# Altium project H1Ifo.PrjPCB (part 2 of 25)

## Sheet IfoAux1.SchDoc: D1800185
size C; Engineer: Daniel Sigg; DocumentNumber: 5; Revision: 4; SheetNumber: 5; SheetTotal: 8
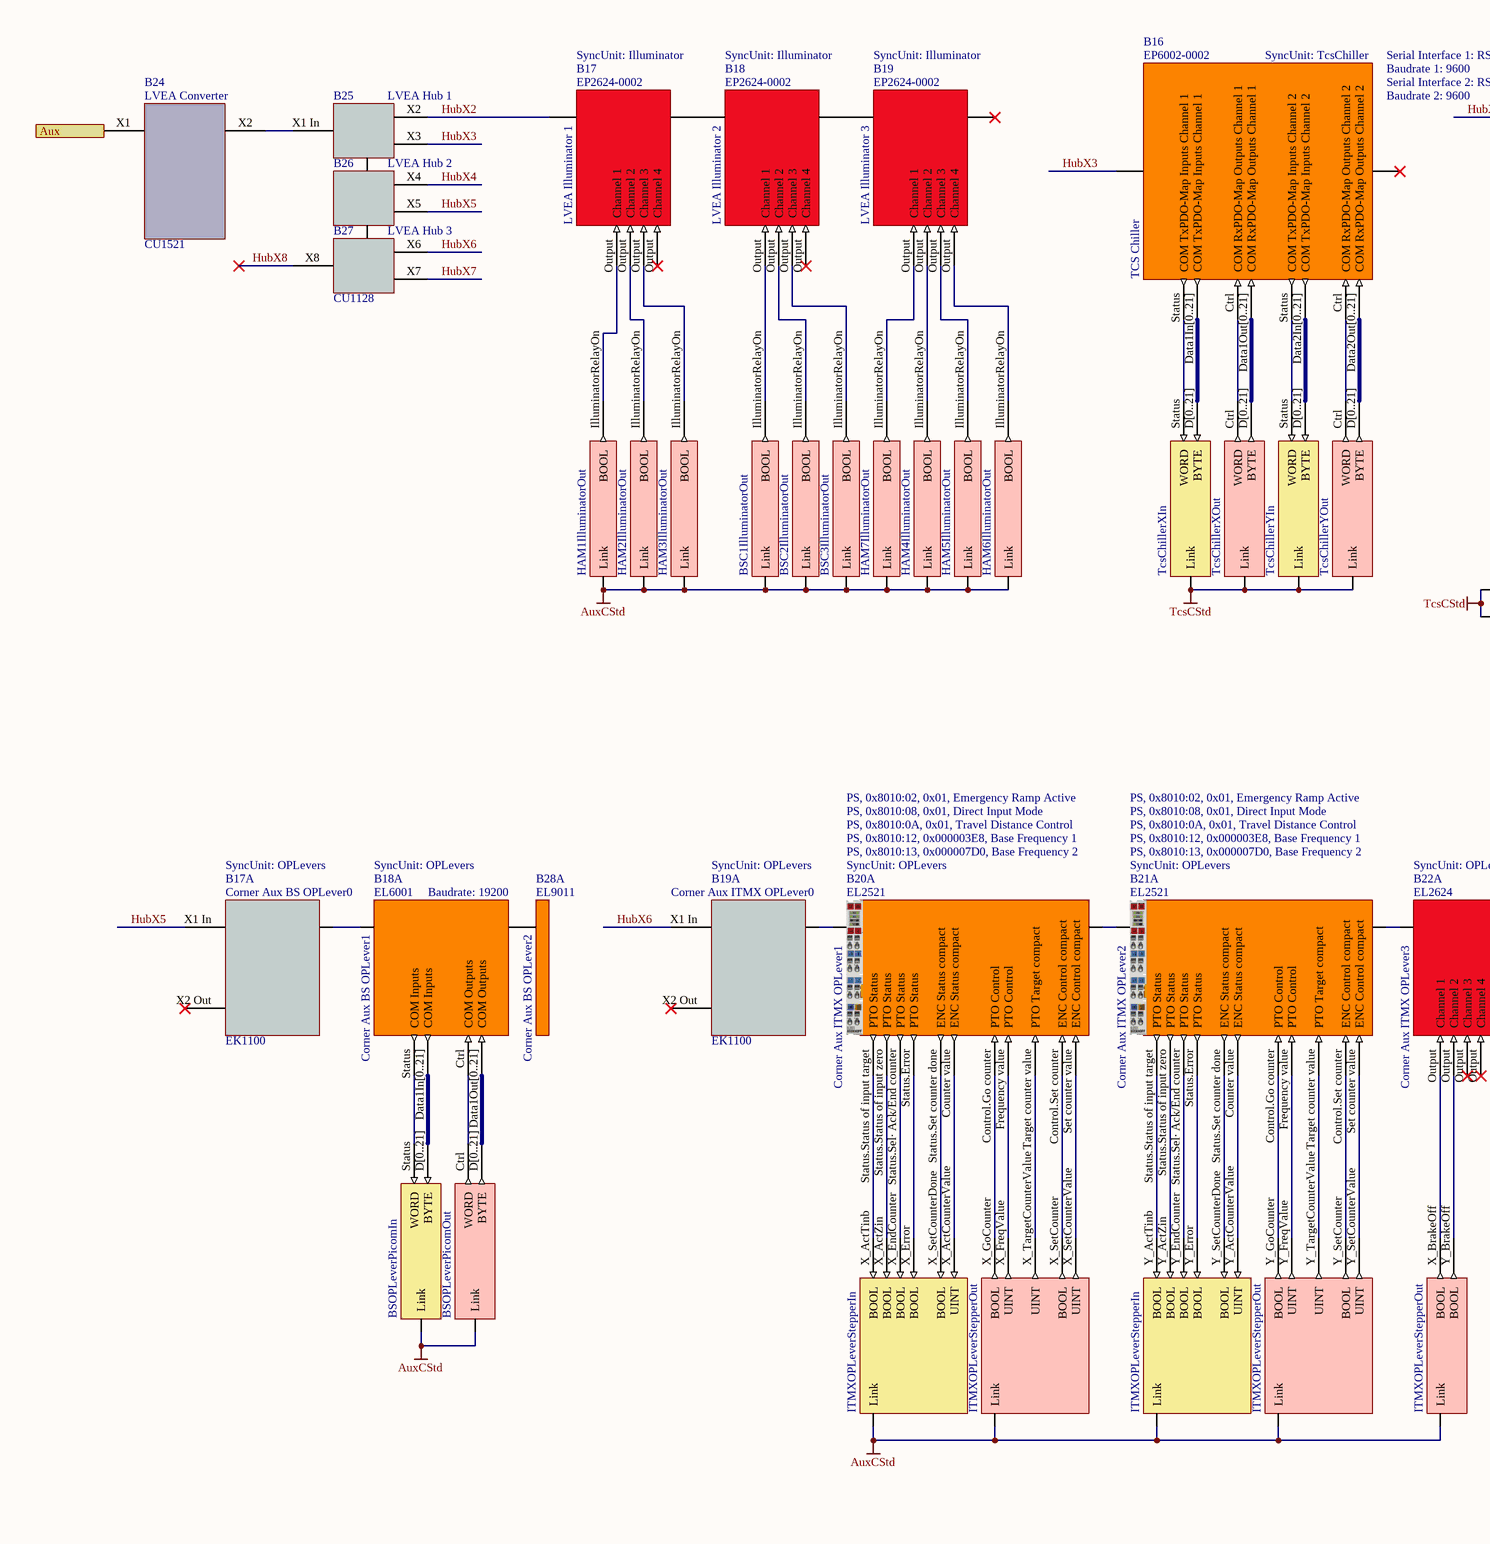
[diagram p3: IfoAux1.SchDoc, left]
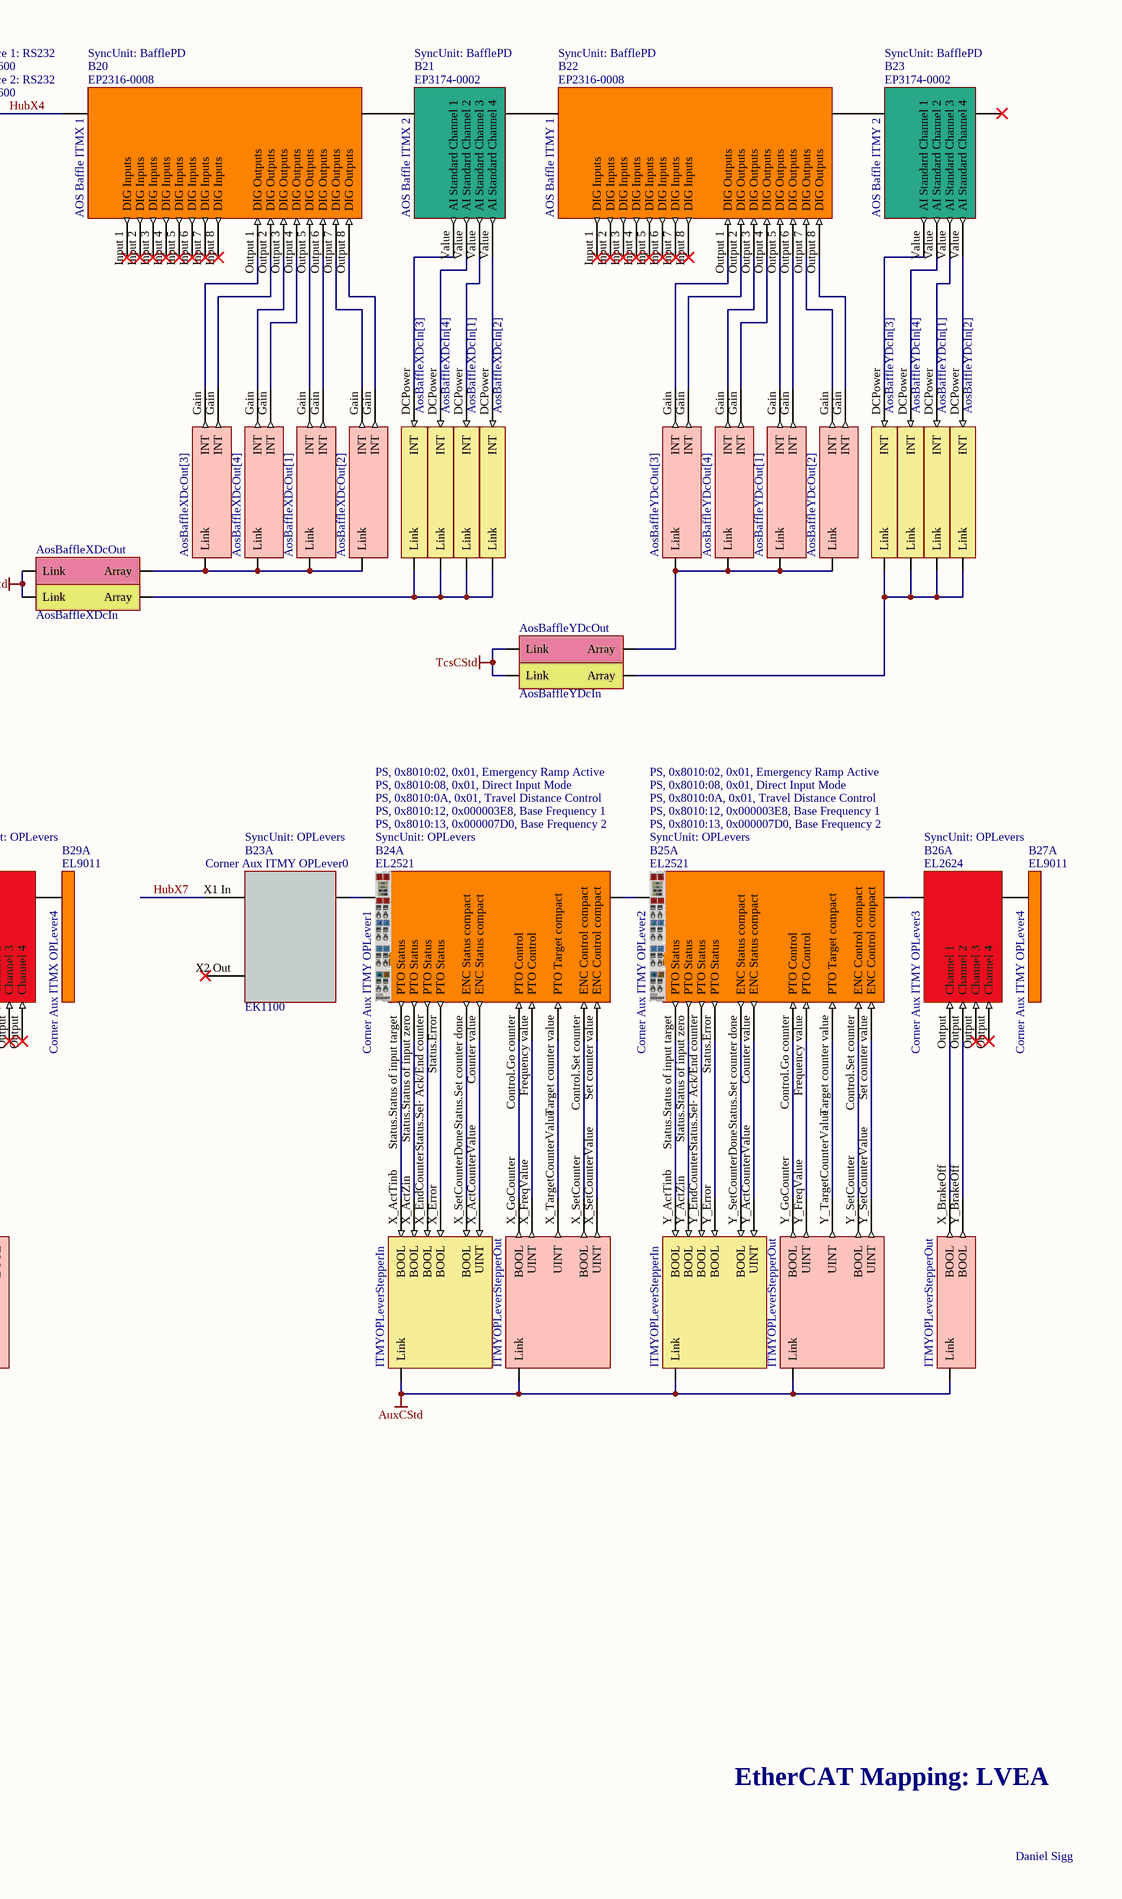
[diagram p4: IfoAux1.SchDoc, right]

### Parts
B16  TCS Chiller  Part Number: EP6002-0002  SyncUnit: TcsChiller  Baudrate 1: 9600  Serial Interface 1: RS232  (mechanical)
B17  LVEA Illuminator 1  Part Number: EP2624-0002  SyncUnit: Illuminator  (mechanical)
B17A  Corner Aux BS OPLever0  SyncUnit: OPLevers  Part Number: EK1100  (mechanical)
B18  LVEA Illuminator 2  Part Number: EP2624-0002  SyncUnit: Illuminator  (mechanical)
B18A  Corner Aux BS OPLever1  SyncUnit: OPLevers  Part Number: EL6001  Baudrate: 19200  (mechanical)
B19  LVEA Illuminator 3  Part Number: EP2624-0002  SyncUnit: Illuminator  (mechanical)
B19A  Corner Aux ITMX OPLever0  SyncUnit: OPLevers  Part Number: EK1100  (mechanical)
B20  AOS Baffle ITMX 1  Part Number: EP2316-0008  SyncUnit: BafflePD  (mechanical)
B20A  Corner Aux ITMX OPLever1  SyncUnit: OPLevers  Part Number: EL2521  Init0Cmd: PS, 0x8010:02, 0x01, Emergency Ramp Active  Init1Cmd: PS, 0x8010:08, 0x01, Direct Input Mode  Init2Cmd: PS, 0x8010:0A, 0x01, Travel Distance Control  Init3Cmd: PS, 0x8010:12, 0x000003E8, Base Frequency 1  Init4Cmd: PS, 0x8010:13, 0x000007D0, Base Frequency 2  (mechanical)
B21  AOS Baffle ITMX 2  Part Number: EP3174-0002  SyncUnit: BafflePD  (mechanical)
B21A  Corner Aux ITMX OPLever2  SyncUnit: OPLevers  Part Number: EL2521  Init0Cmd: PS, 0x8010:02, 0x01, Emergency Ramp Active  Init1Cmd: PS, 0x8010:08, 0x01, Direct Input Mode  Init2Cmd: PS, 0x8010:0A, 0x01, Travel Distance Control  Init3Cmd: PS, 0x8010:12, 0x000003E8, Base Frequency 1  Init4Cmd: PS, 0x8010:13, 0x000007D0, Base Frequency 2  (mechanical)
B22  AOS Baffle ITMY 1  Part Number: EP2316-0008  SyncUnit: BafflePD  (mechanical)
B22A  Corner Aux ITMX OPLever3  SyncUnit: OPLevers  Part Number: EL2624  (mechanical)
B23  AOS Baffle ITMY 2  Part Number: EP3174-0002  SyncUnit: BafflePD  (mechanical)
B23A  Corner Aux ITMY OPLever0  SyncUnit: OPLevers  Part Number: EK1100  (mechanical)
B24  LVEA Converter  Part Number: CU1521  (mechanical)
B24A  Corner Aux ITMY OPLever1  SyncUnit: OPLevers  Part Number: EL2521  Init0Cmd: PS, 0x8010:02, 0x01, Emergency Ramp Active  Init1Cmd: PS, 0x8010:08, 0x01, Direct Input Mode  Init2Cmd: PS, 0x8010:0A, 0x01, Travel Distance Control  Init3Cmd: PS, 0x8010:12, 0x000003E8, Base Frequency 1  Init4Cmd: PS, 0x8010:13, 0x000007D0, Base Frequency 2  (mechanical)
B25  LVEA Hub 1  Part Number: CU1128  (mechanical)
B25A  Corner Aux ITMY OPLever2  SyncUnit: OPLevers  Part Number: EL2521  Init0Cmd: PS, 0x8010:02, 0x01, Emergency Ramp Active  Init1Cmd: PS, 0x8010:08, 0x01, Direct Input Mode  Init2Cmd: PS, 0x8010:0A, 0x01, Travel Distance Control  Init3Cmd: PS, 0x8010:12, 0x000003E8, Base Frequency 1  Init4Cmd: PS, 0x8010:13, 0x000007D0, Base Frequency 2  (mechanical)
B26  LVEA Hub 2  (mechanical)
B26A  Corner Aux ITMY OPLever3  SyncUnit: OPLevers  Part Number: EL2624  (mechanical)
B27  LVEA Hub 3  (mechanical)
B27A  Corner Aux ITMY OPLever4  Part Number: EL9011  (mechanical)
B28A  Corner Aux BS OPLever2  Part Number: EL9011  (mechanical)
B29A  Corner Aux ITMX OPLever4  Part Number: EL9011  (mechanical)
V105  HAM1IlluminatorOut  (no BOM)
V105A  BSOPLeverPicomIn  (no BOM)
V106  HAM2IlluminatorOut  (no BOM)
V106A  BSOPLeverPicomOut  (no BOM)
V107  HAM3IlluminatorOut  (no BOM)
V107A  ITMXOPLeverStepperIn  (parts A,B of 2)  (no BOM)
V108  BSC1IlluminatorOut  (no BOM)
V108A  ITMXOPLeverStepperOut  (parts A,B,C of 3)  (no BOM)
V109  BSC2IlluminatorOut  (no BOM)
V109A  ITMYOPLeverStepperIn  (parts A,B of 2)  (no BOM)
V110  BSC3IlluminatorOut  (no BOM)
V110A  ITMYOPLeverStepperOut  (parts A,B,C of 3)  (no BOM)
V111  HAM4IlluminatorOut  (no BOM)
V112  HAM5IlluminatorOut  (no BOM)
V113  HAM6IlluminatorOut  (no BOM)
V114  AosBaffleXDcOut[3]  (no BOM)
V115  AosBaffleXDcOut[4]  (no BOM)
V116  AosBaffleXDcOut[1]  (no BOM)
V117  AosBaffleXDcOut[2]  (no BOM)
V118  AosBaffleXDcIn[3]  (no BOM)
V119  AosBaffleXDcIn[4]  (no BOM)
V120  AosBaffleXDcIn[1]  (no BOM)
V121  AosBaffleXDcIn[2]  (no BOM)
V122  AosBaffleYDcOut[3]  (no BOM)
V123  AosBaffleYDcOut[4]  (no BOM)
V124  AosBaffleYDcOut[1]  (no BOM)
V129  AosBaffleYDcOut[2]  (no BOM)
V130  AosBaffleYDcIn[3]  (no BOM)
V133  AosBaffleYDcIn[4]  (no BOM)
V134  AosBaffleYDcIn[1]  (no BOM)
V135  AosBaffleYDcIn[2]  (no BOM)
V136  AosBaffleXDcOut  (no BOM)
V137  TcsChillerXIn  (no BOM)
V138  TcsChillerXOut  (no BOM)
V139  TcsChillerYIn  (no BOM)
V140  TcsChillerYOut  (no BOM)
V141  AosBaffleXDcIn  (no BOM)
V142  AosBaffleYDcOut  (no BOM)
V143  AosBaffleYDcIn  (no BOM)
V842  HAM7IlluminatorOut  (no BOM)

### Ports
Aux

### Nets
AuxCStd: V105.0(Link) V105A.?1(Link) V106.0(Link) V106A.?1(Link) V107.0(Link) V107A.0(Link) V107A.1(Link) V108.0(Link) V108A.0(Link) V108A.1(Link) V108A.2(Link) V109.0(Link) V109A.0(Link) V109A.1(Link) V110.0(Link) V110A.0(Link) V110A.1(Link) V110A.2(Link) V111.0(Link) V112.0(Link) V113.0(Link) V842.0(Link)
TcsCStd: V136.?1(Link) V137.?1(Link) V138.?1(Link) V139.?1(Link) V140.?1(Link) V141.?1(Link) V142.?1(Link) V143.?1(Link)
HubX2: B17.?2(A) B25.X2(D)
HubX3: B16.?2(A) B25.X3(B)
HubX4: B20.?2(A) B26.X4(D)
HubX5: B17A.X1_In(A) B26.X5(B)
HubX6: B19A.X1_In(A) B27.X6(D)
HubX7: B23A.X1_In(A) B27.X7(B)
HubX8: B27.X8(C)
NetB16_Ctrl: B16.Ctrl(COM_RxPDO-Map_Outputs_Channel_1) V138.Ctrl(WORD)
NetB16_Ctrl: B16.Ctrl(COM_RxPDO-Map_Outputs_Channel_2) V140.Ctrl(WORD)  [a separate net that carries the same name]
NetB16_Data1In[0..21]: B16.Data1In[0..21](COM_TxPDO-Map_Inputs_Channel_1) V137.D[0..21](BYTE)
NetB16_Data1Out[0..21]: B16.Data1Out[0..21](COM_RxPDO-Map_Outputs_Channel_1) V138.D[0..21](BYTE)
NetB16_Data2In[0..21]: B16.Data2In[0..21](COM_TxPDO-Map_Inputs_Channel_2) V139.D[0..21](BYTE)
NetB16_Data2Out[0..21]: B16.Data2Out[0..21](COM_RxPDO-Map_Outputs_Channel_2) V140.D[0..21](BYTE)
NetB16_Status: B16.Status(COM_TxPDO-Map_Inputs_Channel_1) V137.Status(WORD)
NetB16_Status: B16.Status(COM_TxPDO-Map_Inputs_Channel_2) V139.Status(WORD)  [a separate net that carries the same name]
NetB17_?1: B17.?1(B) B18.?2(A)
NetB17_Output: B17.Output(Channel_1) V105.IlluminatorRelayOn(BOOL)
NetB17_Output: B17.Output(Channel_2) V106.IlluminatorRelayOn(BOOL)  [a separate net that carries the same name]
NetB17_Output: B17.Output(Channel_3) V107.IlluminatorRelayOn(BOOL)  [a separate net that carries the same name]
NetB17A_Ebus: B17A.Ebus(B) B18A.Ebus(A)
NetB18_?1: B18.?1(B) B19.?2(A)
NetB18_Output: B18.Output(Channel_1) V108.IlluminatorRelayOn(BOOL)
NetB18_Output: B18.Output(Channel_2) V109.IlluminatorRelayOn(BOOL)  [a separate net that carries the same name]
NetB18_Output: B18.Output(Channel_3) V110.IlluminatorRelayOn(BOOL)  [a separate net that carries the same name]
NetB18A_Ctrl: B18A.Ctrl(COM_Outputs) V106A.Ctrl(WORD)
NetB18A_Data1In[0..21]: B18A.Data1In[0..21](COM_Inputs) V105A.D[0..21](BYTE)
NetB18A_Data1Out[0..21]: B18A.Data1Out[0..21](COM_Outputs) V106A.D[0..21](BYTE)
NetB18A_Ebus: B18A.Ebus(B) B28A.Ebus(A)
NetB18A_Status: B18A.Status(COM_Inputs) V105A.Status(WORD)
NetB19_Output: B19.Output(Channel_1) V842.IlluminatorRelayOn(BOOL)
NetB19_Output: B19.Output(Channel_2) V111.IlluminatorRelayOn(BOOL)  [a separate net that carries the same name]
NetB19_Output: B19.Output(Channel_3) V112.IlluminatorRelayOn(BOOL)  [a separate net that carries the same name]
NetB19_Output: B19.Output(Channel_4) V113.IlluminatorRelayOn(BOOL)  [a separate net that carries the same name]
NetB19A_Ebus: B19A.Ebus(B) B20A.Ebus(A)
NetB20_?1: B20.?1(B) B21.?2(A)
NetB20_Output 1: B20.Output_1(DIG_Outputs) V114.Gain(INT)
NetB20_Output 2: B20.Output_2(DIG_Outputs) V114.Gain(INT)
NetB20_Output 3: B20.Output_3(DIG_Outputs) V115.Gain(INT)
NetB20_Output 4: B20.Output_4(DIG_Outputs) V115.Gain(INT)
NetB20_Output 5: B20.Output_5(DIG_Outputs) V116.Gain(INT)
NetB20_Output 6: B20.Output_6(DIG_Outputs) V116.Gain(INT)
NetB20_Output 7: B20.Output_7(DIG_Outputs) V117.Gain(INT)
NetB20_Output 8: B20.Output_8(DIG_Outputs) V117.Gain(INT)
NetB20A_Control.Go counter: B20A.Control.Go_counter(PTO_Control) V108A.X_GoCounter(BOOL)
NetB20A_Control.Set counter: B20A.Control.Set_counter(ENC_Control_compact) V108A.X_SetCounter(BOOL)
NetB20A_Counter value: B20A.Counter_value(ENC_Status_compact) V107A.X_ActCounterValue(UINT)
NetB20A_Ebus: B20A.Ebus(B) B21A.Ebus(A)
NetB20A_Frequency value: B20A.Frequency_value(PTO_Control) V108A.X_FreqValue(UINT)
NetB20A_Set counter value: B20A.Set_counter_value(ENC_Control_compact) V108A.X_SetCounterValue(UINT)
NetB20A_Status.Error: B20A.Status.Error(PTO_Status) V107A.X_Error(BOOL)
NetB20A_Status.Sel· Ack/End counter: B20A.Status.Sel·_Ack/End_counter(PTO_Status) V107A.X_EndCounter(BOOL)
NetB20A_Status.Set counter done: B20A.Status.Set_counter_done(ENC_Status_compact) V107A.X_SetCounterDone(BOOL)
NetB20A_Status.Status of input target: B20A.Status.Status_of_input_target(PTO_Status) V107A.X_ActTinb(BOOL)
NetB20A_Status.Status of input zero: B20A.Status.Status_of_input_zero(PTO_Status) V107A.X_ActZin(BOOL)
NetB20A_Target counter value: B20A.Target_counter_value(PTO_Target_compact) V108A.X_TargetCounterValue(UINT)
NetB21_?1: B21.?1(B) B22.?2(A)
NetB21_Value: B21.Value(AI_Standard_Channel_1) V118.DCPower(INT)
NetB21_Value: B21.Value(AI_Standard_Channel_2) V119.DCPower(INT)  [a separate net that carries the same name]
NetB21_Value: B21.Value(AI_Standard_Channel_3) V120.DCPower(INT)  [a separate net that carries the same name]
NetB21_Value: B21.Value(AI_Standard_Channel_4) V121.DCPower(INT)  [a separate net that carries the same name]
NetB21A_Control.Go counter: B21A.Control.Go_counter(PTO_Control) V108A.Y_GoCounter(BOOL)
NetB21A_Control.Set counter: B21A.Control.Set_counter(ENC_Control_compact) V108A.Y_SetCounter(BOOL)
NetB21A_Counter value: B21A.Counter_value(ENC_Status_compact) V107A.Y_ActCounterValue(UINT)
NetB21A_Ebus: B21A.Ebus(B) B22A.Ebus(A)
NetB21A_Frequency value: B21A.Frequency_value(PTO_Control) V108A.Y_FreqValue(UINT)
NetB21A_Set counter value: B21A.Set_counter_value(ENC_Control_compact) V108A.Y_SetCounterValue(UINT)
NetB21A_Status.Error: B21A.Status.Error(PTO_Status) V107A.Y_Error(BOOL)
NetB21A_Status.Sel· Ack/End counter: B21A.Status.Sel·_Ack/End_counter(PTO_Status) V107A.Y_EndCounter(BOOL)
NetB21A_Status.Set counter done: B21A.Status.Set_counter_done(ENC_Status_compact) V107A.Y_SetCounterDone(BOOL)
NetB21A_Status.Status of input target: B21A.Status.Status_of_input_target(PTO_Status) V107A.Y_ActTinb(BOOL)
NetB21A_Status.Status of input zero: B21A.Status.Status_of_input_zero(PTO_Status) V107A.Y_ActZin(BOOL)
NetB21A_Target counter value: B21A.Target_counter_value(PTO_Target_compact) V108A.Y_TargetCounterValue(UINT)
NetB22_?1: B22.?1(B) B23.?2(A)
NetB22_Output 1: B22.Output_1(DIG_Outputs) V122.Gain(INT)
NetB22_Output 2: B22.Output_2(DIG_Outputs) V122.Gain(INT)
NetB22_Output 3: B22.Output_3(DIG_Outputs) V123.Gain(INT)
NetB22_Output 4: B22.Output_4(DIG_Outputs) V123.Gain(INT)
NetB22_Output 5: B22.Output_5(DIG_Outputs) V124.Gain(INT)
NetB22_Output 6: B22.Output_6(DIG_Outputs) V124.Gain(INT)
NetB22_Output 7: B22.Output_7(DIG_Outputs) V129.Gain(INT)
NetB22_Output 8: B22.Output_8(DIG_Outputs) V129.Gain(INT)
NetB22A_Ebus: B22A.Ebus(B) B29A.Ebus(A)
NetB22A_Output: B22A.Output(Channel_1) V108A.X_BrakeOff(BOOL)
NetB22A_Output: B22A.Output(Channel_2) V108A.Y_BrakeOff(BOOL)  [a separate net that carries the same name]
NetB23_Value: B23.Value(AI_Standard_Channel_1) V130.DCPower(INT)
NetB23_Value: B23.Value(AI_Standard_Channel_2) V133.DCPower(INT)  [a separate net that carries the same name]
NetB23_Value: B23.Value(AI_Standard_Channel_3) V134.DCPower(INT)  [a separate net that carries the same name]
NetB23_Value: B23.Value(AI_Standard_Channel_4) V135.DCPower(INT)  [a separate net that carries the same name]
NetB23A_Ebus: B23A.Ebus(B) B24A.Ebus(A)
NetB24_X1: B24.X1(A) ; port Aux
NetB24_X2: B24.X2(B) B25.X1_In(A)
NetB24A_Control.Go counter: B24A.Control.Go_counter(PTO_Control) V110A.X_GoCounter(BOOL)
NetB24A_Control.Set counter: B24A.Control.Set_counter(ENC_Control_compact) V110A.X_SetCounter(BOOL)
NetB24A_Counter value: B24A.Counter_value(ENC_Status_compact) V109A.X_ActCounterValue(UINT)
NetB24A_Ebus: B24A.Ebus(B) B25A.Ebus(A)
NetB24A_Frequency value: B24A.Frequency_value(PTO_Control) V110A.X_FreqValue(UINT)
NetB24A_Set counter value: B24A.Set_counter_value(ENC_Control_compact) V110A.X_SetCounterValue(UINT)
NetB24A_Status.Error: B24A.Status.Error(PTO_Status) V109A.X_Error(BOOL)
NetB24A_Status.Sel· Ack/End counter: B24A.Status.Sel·_Ack/End_counter(PTO_Status) V109A.X_EndCounter(BOOL)
NetB24A_Status.Set counter done: B24A.Status.Set_counter_done(ENC_Status_compact) V109A.X_SetCounterDone(BOOL)
NetB24A_Status.Status of input target: B24A.Status.Status_of_input_target(PTO_Status) V109A.X_ActTinb(BOOL)
NetB24A_Status.Status of input zero: B24A.Status.Status_of_input_zero(PTO_Status) V109A.X_ActZin(BOOL)
NetB24A_Target counter value: B24A.Target_counter_value(PTO_Target_compact) V110A.X_TargetCounterValue(UINT)
NetB25_Ebus: B25.Ebus(C) B26.Ebus(A)
NetB25A_Control.Go counter: B25A.Control.Go_counter(PTO_Control) V110A.Y_GoCounter(BOOL)
NetB25A_Control.Set counter: B25A.Control.Set_counter(ENC_Control_compact) V110A.Y_SetCounter(BOOL)
NetB25A_Counter value: B25A.Counter_value(ENC_Status_compact) V109A.Y_ActCounterValue(UINT)
NetB25A_Ebus: B25A.Ebus(B) B26A.Ebus(A)
NetB25A_Frequency value: B25A.Frequency_value(PTO_Control) V110A.Y_FreqValue(UINT)
NetB25A_Set counter value: B25A.Set_counter_value(ENC_Control_compact) V110A.Y_SetCounterValue(UINT)
NetB25A_Status.Error: B25A.Status.Error(PTO_Status) V109A.Y_Error(BOOL)
NetB25A_Status.Sel· Ack/End counter: B25A.Status.Sel·_Ack/End_counter(PTO_Status) V109A.Y_EndCounter(BOOL)
NetB25A_Status.Set counter done: B25A.Status.Set_counter_done(ENC_Status_compact) V109A.Y_SetCounterDone(BOOL)
NetB25A_Status.Status of input target: B25A.Status.Status_of_input_target(PTO_Status) V109A.Y_ActTinb(BOOL)
NetB25A_Status.Status of input zero: B25A.Status.Status_of_input_zero(PTO_Status) V109A.Y_ActZin(BOOL)
NetB25A_Target counter value: B25A.Target_counter_value(PTO_Target_compact) V110A.Y_TargetCounterValue(UINT)
NetB26_Ebus: B26.Ebus(C) B27.Ebus(A)
NetB26A_Ebus: B26A.Ebus(B) B27A.Ebus(A)
NetB26A_Output: B26A.Output(Channel_1) V110A.X_BrakeOff(BOOL)
NetB26A_Output: B26A.Output(Channel_2) V110A.Y_BrakeOff(BOOL)  [a separate net that carries the same name]
NetV114_0: V114.0(Link) V115.0(Link) V116.0(Link) V117.0(Link) V136.?2(Array)
NetV118_1: V118.1(Link) V119.1(Link) V120.1(Link) V121.1(Link) V141.?2(Array)
NetV122_0: V122.0(Link) V123.0(Link) V124.0(Link) V129.0(Link) V142.?2(Array)
NetV130_1: V130.1(Link) V133.1(Link) V134.1(Link) V135.1(Link) V143.?2(Array)

Not connected (* = marked no-connect by the designer): B16 ?1(B)*; B17A X2 Out(C)*; B19 ?1(B)*; B19A X2 Out(C)*; B20 Input 1(DIG_Inputs)* Input 2(DIG_Inputs)* Input 3(DIG_Inputs)* Input 4(DIG_Inputs)* Input 5(DIG_Inputs)* Input 6(DIG_Inputs)* Input 7(DIG_Inputs)* Input 8(DIG_Inputs)*; B22 Input 1(DIG_Inputs)* Input 2(DIG_Inputs)* Input 3(DIG_Inputs)* Input 4(DIG_Inputs)* Input 5(DIG_Inputs)* Input 6(DIG_Inputs)* Input 7(DIG_Inputs)* Input 8(DIG_Inputs)*; B23 ?1(B)*; B23A X2 Out(C)*

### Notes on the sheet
- EtherCAT Mapping: LVEA
- Daniel Sigg

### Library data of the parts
B16 = BoxEP6002-0002: EtherCAT Box EP6002-0002 2-channel serial interface, RS232, RS422/RS485; BoxPrev: FNEMRSPV; PortPrevFull: 1003/B; PortPrevShort: B 'X3'; Fullname: TIID^Vertex Auxiliary (EtherCAT)^LVEA Hub 1 (CU1128)^TCS Chiller (EP6002-0002); BoxAddr: 1007; BoxSubType: 9101; Disabled: False
B17 = BoxEP2624-0002: EtherCAT Box EP2624-0002 4-channel relay output 25 V AC/30 V DC; BoxNextB: DKDGOXWB; BoxPrev: FNEMRSPV; PortPrevFull: 1003/D; PortPrevShort: D 'X2'; Fullname: TIID^Vertex Auxiliary (EtherCAT)^LVEA Hub 1 (CU1128)^LVEA Illuminator 1 (EP2624-0002); BoxAddr: 1004; Disabled: False
B17A = CouplerEK1100: EtherCAT Coupler; BoxNextB: COSNHDNC; BoxPrev: FDYVWJUW; PortPrevFull: 1008/B; PortPrevShort: B 'X5'; Fullname: TIID^Vertex Auxiliary (EtherCAT)^LVEA Hub 1 (CU1128)^LVEA Hub 2 (CU1128-0001)^Corner Aux BS OPLever0 (EK1100); BoxPorts: Junction; BoxAddr: 1013; Disabled: False
B18 = BoxEP2624-0002: EtherCAT Box EP2624-0002 4-channel relay output 25 V AC/30 V DC; BoxNextB: JASQJGFQ; BoxPrev: XHXLFGRF; PortPrevFull: 1004/B; PortPrevShort: B; Fullname: TIID^Vertex Auxiliary (EtherCAT)^LVEA Hub 1 (CU1128)^LVEA Illuminator 2 (EP2624-0002); BoxAddr: 1005; Disabled: False
B18A = TerminalEL6001: EtherCAT Terminal EL6001 1CH RS232; BoxNextB: SAOREKEC; BoxPrev: AXCQBPJJ; PortPrevFull: 1013/B; PortPrevShort: B; Fullname: TIID^Vertex Auxiliary (EtherCAT)^LVEA Hub 1 (CU1128)^LVEA Hub 2 (CU1128-0001)^Corner Aux BS OPLever0 (EK1100)^Corner Aux BS OPLever1 (EL6001); BoxAddr: 1014; BoxSubType: 9101; Disabled: False
B19 = BoxEP2624-0002: EtherCAT Box EP2624-0002 4-channel relay output 25 V AC/30 V DC; BoxPrev: DKDGOXWB; PortPrevFull: 1005/B; PortPrevShort: B; Fullname: TIID^Vertex Auxiliary (EtherCAT)^LVEA Hub 1 (CU1128)^LVEA Illuminator 3 (EP2624-0002); BoxAddr: 1006; Disabled: False
B19A = CouplerEK1100: EtherCAT Coupler; BoxNextB: GEMUKCRY; BoxPrev: TMRSKTIB; PortPrevFull: 1015/D; PortPrevShort: D 'X6'; Fullname: TIID^Vertex Auxiliary (EtherCAT)^LVEA Hub 1 (CU1128)^LVEA Hub 3 (CU1128-0002)^Corner Aux ITMX OPLever0 (EK1100); BoxPorts: Junction; BoxAddr: 1016; Disabled: False
B20 = BoxEP2316-0008: EtherCAT Box EP2316-0008 8 x digital input + 8 x digital output; BoxNextB: KVHCFKIY; BoxPrev: FDYVWJUW; PortPrevFull: 1008/D; PortPrevShort: D 'X4'; Fullname: TIID^Vertex Auxiliary (EtherCAT)^LVEA Hub 1 (CU1128)^LVEA Hub 2 (CU1128-0001)^AOS Baffle ITMX 1 (EP2316-0008); BoxAddr: 1009; Disabled: False
B20A = TerminalEL2521: EtherCAT Terminal EL2521 1-channel pulse train output, incr. enc. simulation, RS422, 50 mA; BoxNextB: UHHNAPRC; BoxPrev: LUHQMILF; PortPrevFull: 1016/B; PortPrevShort: B; Fullname: TIID^Vertex Auxiliary (EtherCAT)^LVEA Hub 1 (CU1128)^LVEA Hub 3 (CU1128-0002)^Corner Aux ITMX OPLever0 (EK1100)^Corner Aux ITMX OPLever1 (EL2521); BoxAddr: 1017; PDO Outputs: 0x1601,0x1604,0x1602; PDO Inputs: 0x1A01,0x1A02; Disabled: False
B21 = BoxEP3174-0002: EtherCAT Box EP3174-0002 4-channel analog input ±10 V or 0/4…20 mA, parameterisable, differential input, 16 bit; BoxNextB: AOFKUTNX; BoxPrev: GLCBWCJX; PortPrevFull: 1009/B; PortPrevShort: B; Fullname: TIID^Vertex Auxiliary (EtherCAT)^LVEA Hub 1 (CU1128)^LVEA Hub 2 (CU1128-0001)^AOS Baffle ITMX 2 (EP3174-0002); BoxAddr: 1010; Disabled: False
B21A = TerminalEL2521: EtherCAT Terminal EL2521 1-channel pulse train output, incr. enc. simulation, RS422, 50 mA; BoxNextB: WUQRNLWF; BoxPrev: GEMUKCRY; PortPrevFull: 1017/B; PortPrevShort: B; Fullname: TIID^Vertex Auxiliary (EtherCAT)^LVEA Hub 1 (CU1128)^LVEA Hub 3 (CU1128-0002)^Corner Aux ITMX OPLever0 (EK1100)^Corner Aux ITMX OPLever2 (EL2521); BoxAddr: 1018; PDO Outputs: 0x1601,0x1604,0x1602; PDO Inputs: 0x1A01,0x1A02; Disabled: False
B22 = BoxEP2316-0008: EtherCAT Box EP2316-0008 8 x digital input + 8 x digital output; BoxNextB: MOPURVEU; BoxPrev: KVHCFKIY; PortPrevFull: 1010/B; PortPrevShort: B; Fullname: TIID^Vertex Auxiliary (EtherCAT)^LVEA Hub 1 (CU1128)^LVEA Hub 2 (CU1128-0001)^AOS Baffle ITMY 1 (EP2316-0008); BoxAddr: 1011; Disabled: False
B22A = TerminalEL2624: EtherCAT Terminal EL2624 4-channel relay output terminal 125 V AC/30 V DC; BoxNextB: PFWLIIWO; BoxPrev: UHHNAPRC; PortPrevFull: 1018/B; PortPrevShort: B; Fullname: TIID^Vertex Auxiliary (EtherCAT)^LVEA Hub 1 (CU1128)^LVEA Hub 3 (CU1128-0002)^Corner Aux ITMX OPLever0 (EK1100)^Corner Aux ITMX OPLever3 (EL2624); BoxAddr: 1019; Disabled: False
B23 = BoxEP3174-0002: EtherCAT Box EP3174-0002 4-channel analog input ±10 V or 0/4…20 mA, parameterisable, differential input, 16 bit; BoxPrev: AOFKUTNX; PortPrevFull: 1011/B; PortPrevShort: B; Fullname: TIID^Vertex Auxiliary (EtherCAT)^LVEA Hub 1 (CU1128)^LVEA Hub 2 (CU1128-0001)^AOS Baffle ITMY 2 (EP3174-0002); BoxAddr: 1012; Disabled: False
B23A = CouplerEK1100: EtherCAT Coupler; BoxNextB: ZUKLOFPW; BoxPrev: TMRSKTIB; PortPrevFull: 1015/B; PortPrevShort: B 'X7'; Fullname: TIID^Vertex Auxiliary (EtherCAT)^LVEA Hub 1 (CU1128)^LVEA Hub 3 (CU1128-0002)^Corner Aux ITMY OPLever0 (EK1100); BoxPorts: Junction; BoxAddr: 1020; Disabled: False
B24 = MediaConverterFiberToCAT5: EtherCAT Media Converter; BoxType: Box; BoxNextB: FNEMRSPV; BoxPrev: NSXPNOPV; PortPrevFull: 1001/B; PortPrevShort: B 'X1'; Fullname: TIID^Vertex Auxiliary (EtherCAT)^LVEA Converter (CU1521); BoxAddr: 1002; Disabled: False
B24A = TerminalEL2521: EtherCAT Terminal EL2521 1-channel pulse train output, incr. enc. simulation, RS422, 50 mA; BoxNextB: FCDAYYGL; BoxPrev: MGGGBBHA; PortPrevFull: 1020/B; PortPrevShort: B; Fullname: TIID^Vertex Auxiliary (EtherCAT)^LVEA Hub 1 (CU1128)^LVEA Hub 3 (CU1128-0002)^Corner Aux ITMY OPLever0 (EK1100)^Corner Aux ITMY OPLever1 (EL2521); BoxAddr: 1021; PDO Outputs: 0x1601,0x1604,0x1602; PDO Inputs: 0x1A01,0x1A02; Disabled: False
B25 = HubCU1128: EtherCAT Hub; BoxType: Box; BoxNextB: YOFAMRMC; BoxNextC: FDYVWJUW; BoxNextD: XHXLFGRF; BoxPrev: RINAXMQE; PortPrevFull: 1002/B; PortPrevShort: B 'X2'; Fullname: TIID^Vertex Auxiliary (EtherCAT)^LVEA Hub 1 (CU1128); BoxPorts: Junction; BoxAddr: 1003; Disabled: False
B25A = TerminalEL2521: EtherCAT Terminal EL2521 1-channel pulse train output, incr. enc. simulation, RS422, 50 mA; BoxNextB: XTHZVPFK; BoxPrev: ZUKLOFPW; PortPrevFull: 1021/B; PortPrevShort: B; Fullname: TIID^Vertex Auxiliary (EtherCAT)^LVEA Hub 1 (CU1128)^LVEA Hub 3 (CU1128-0002)^Corner Aux ITMY OPLever0 (EK1100)^Corner Aux ITMY OPLever2 (EL2521); BoxAddr: 1022; PDO Outputs: 0x1601,0x1604,0x1602; PDO Inputs: 0x1A01,0x1A02; Disabled: False
B26 = HubCU1128-B: EtherCAT Hub subpart B; Part Number: CU1128-0001; BoxType: Box; BoxNextB: AXCQBPJJ; BoxNextC: TMRSKTIB; BoxNextD: GLCBWCJX; BoxPrev: FNEMRSPV; PortPrevFull: 1003/C; PortPrevShort: C; Fullname: TIID^Vertex Auxiliary (EtherCAT)^LVEA Hub 1 (CU1128)^LVEA Hub 2 (CU1128-0001); BoxPorts: Junction; BoxAddr: 1008; Disabled: False
B26A = TerminalEL2624: EtherCAT Terminal EL2624 4-channel relay output terminal 125 V AC/30 V DC; BoxNextB: ENANTINU; BoxPrev: FCDAYYGL; PortPrevFull: 1022/B; PortPrevShort: B; Fullname: TIID^Vertex Auxiliary (EtherCAT)^LVEA Hub 1 (CU1128)^LVEA Hub 3 (CU1128-0002)^Corner Aux ITMY OPLever0 (EK1100)^Corner Aux ITMY OPLever3 (EL2624); BoxAddr: 1023; Disabled: False
B27 = HubCU1128-C: EtherCAT Hub subpart C; Part Number: CU1128-0002; BoxType: Box; BoxNextB: MGGGBBHA; BoxNextD: LUHQMILF; BoxPrev: FDYVWJUW; PortPrevFull: 1008/C; Fullname: TIID^Vertex Auxiliary (EtherCAT)^LVEA Hub 1 (CU1128)^LVEA Hub 3 (CU1128-0002); BoxPorts: Junction; BoxAddr: 1015; Disabled: False
B27A = TerminalEL9011: EtherCAT Terminal EL9011 End; BoxType: TerminalPassive; BoxPrev: XTHZVPFK; PortPrevShort: B; Fullname: TIID^Vertex Auxiliary (EtherCAT)^LVEA Hub 1 (CU1128)^LVEA Hub 3 (CU1128-0002)^Corner Aux ITMY OPLever0 (EK1100)^Corner Aux ITMY OPLever4 (EL9011); Disabled: False
B28A = TerminalEL9011: EtherCAT Terminal EL9011 End; BoxType: TerminalPassive; BoxPrev: COSNHDNC; PortPrevShort: B; Fullname: TIID^Vertex Auxiliary (EtherCAT)^LVEA Hub 1 (CU1128)^LVEA Hub 2 (CU1128-0001)^Corner Aux BS OPLever0 (EK1100)^Corner Aux BS OPLever2 (EL9011); Disabled: False
B29A = TerminalEL9011: EtherCAT Terminal EL9011 End; BoxType: TerminalPassive; BoxPrev: WUQRNLWF; PortPrevShort: B; Fullname: TIID^Vertex Auxiliary (EtherCAT)^LVEA Hub 1 (CU1128)^LVEA Hub 3 (CU1128-0002)^Corner Aux ITMX OPLever0 (EK1100)^Corner Aux ITMX OPLever4 (EL9011); Disabled: False
V105-V113 V842 = Illuminator_IlluminatorOutStruct: IlluminatorOutStruct; BoxType: Variable; Instance: H1AuxCorner Instance; PLC: H1AuxCorner; Task: AuxCStd
V105A = Serial_EL6inData22B: EL6inData22B; BoxType: Variable; Instance: H1AuxCorner Instance; PLC: H1AuxCorner; Task: AuxCStd
V106A = Serial_EL6outData22B: EL6outData22B; BoxType: Variable; Instance: H1AuxCorner Instance; PLC: H1AuxCorner; Task: AuxCStd
V107A V109A = OPLever_OPLeverStepperInStruct: OPLeverStepperInStruct; BoxType: Variable; Instance: H1AuxCorner Instance; PLC: H1AuxCorner; Task: AuxCStd
V108A V110A = OPLever_OPLeverStepperOutStruct: OPLeverStepperOutStruct; BoxType: Variable; Instance: H1AuxCorner Instance; PLC: H1AuxCorner; Task: AuxCStd
V114-V117 V122-V124 V129 = DCPower_DCPowerOutStruct: DCPowerOutStruct; BoxType: Variable; Instance: H1TcsCorner Instance; PLC: H1TcsCorner; Task: TcsCStd
V118-V121 V130 V133-V135 = DCPower_DCPowerInStruct: DCPowerInStruct; BoxType: Variable; Instance: H1TcsCorner Instance; PLC: H1TcsCorner; Task: TcsCStd
V136 V142 = ArrayAggregatorOut: Array [1..4] Of DCPowerOutStruct; Instance: H1TcsCorner Instance; PLC: H1TcsCorner; Task: TcsCStd; Lower Bound: 1; Upper Bound: 4
V137 V139 = Serial_EL6inData22B: EL6inData22B; PLC: H1TcsCorner; Task: TcsCStd; BoxType: Variable; Instance: H1TcsCorner Instance
V138 V140 = Serial_EL6outData22B: EL6outData22B; PLC: H1TcsCorner; Task: TcsCStd; BoxType: Variable; Instance: H1TcsCorner Instance
V141 V143 = ArrayAggregatorIn: Array [1..4] Of DCPowerInStruct; Instance: H1TcsCorner Instance; PLC: H1TcsCorner; Task: TcsCStd; Lower Bound: 1; Upper Bound: 4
